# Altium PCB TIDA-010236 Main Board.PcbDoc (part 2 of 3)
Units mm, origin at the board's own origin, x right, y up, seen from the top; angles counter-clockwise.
Board outline 180 x 120 mm, 2 copper layers (Top Layer, Bottom Layer), stack 1.571 mm thick; 265 components, 145 nets, 704 pads, 547 vias.
Unrouted connection lines stored in the file: 155.
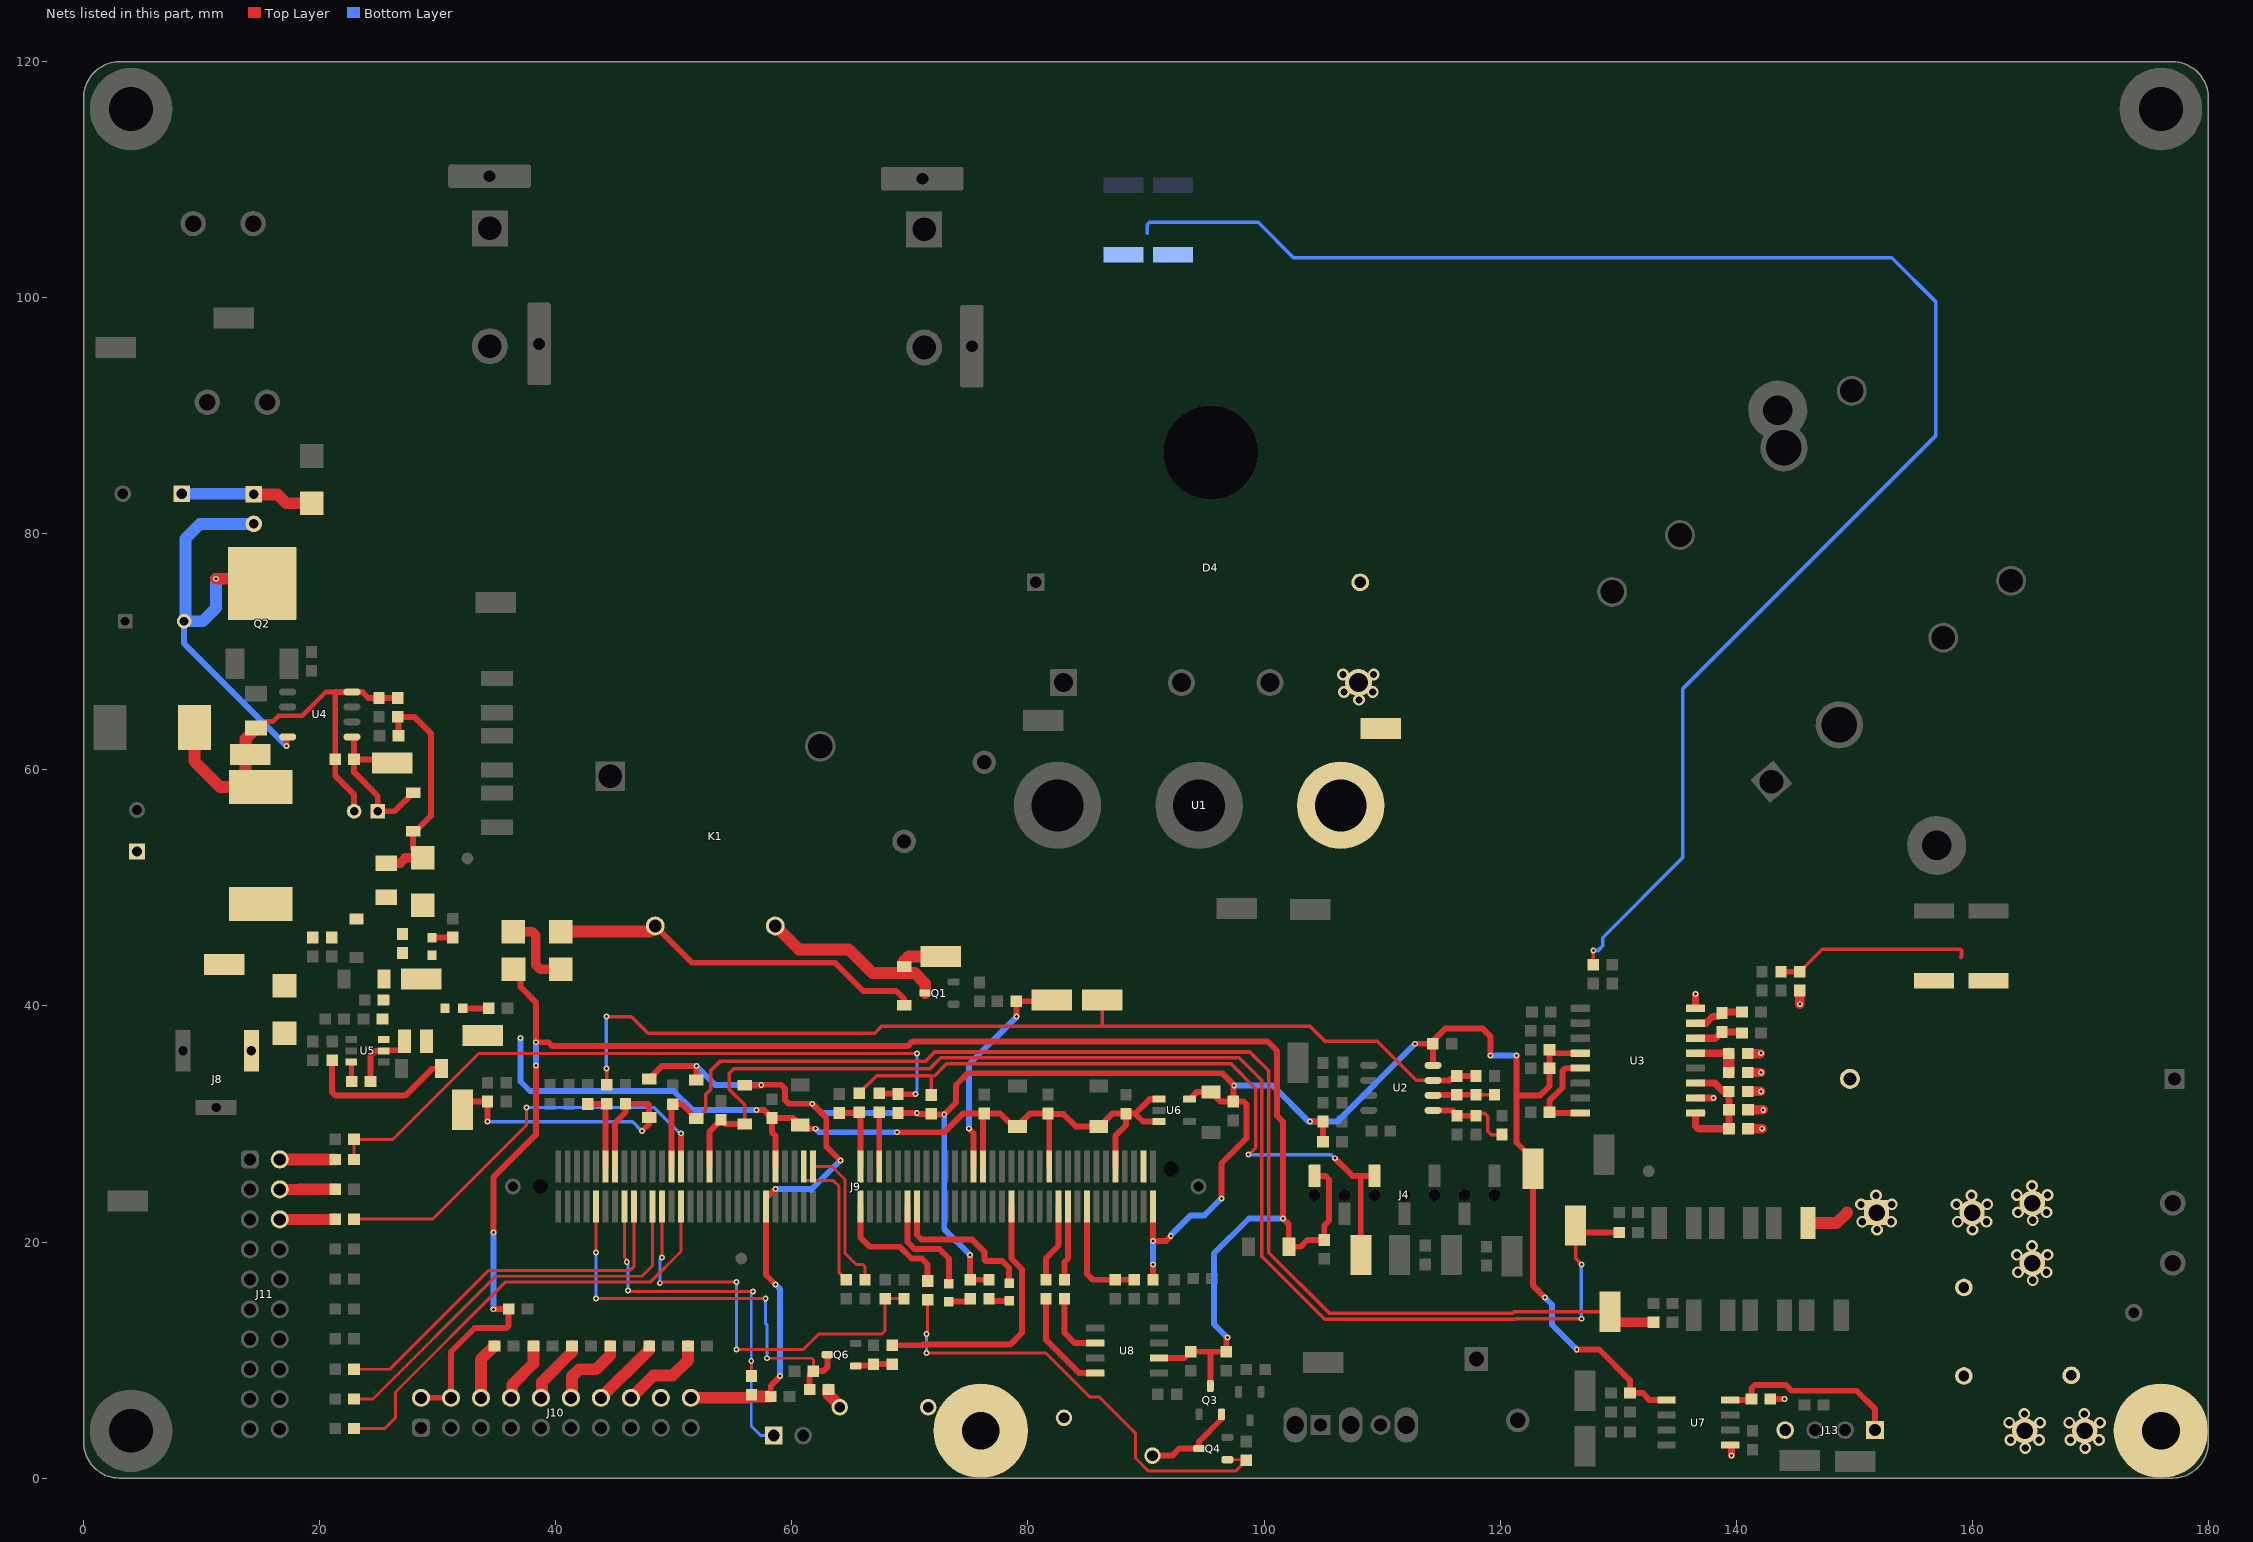
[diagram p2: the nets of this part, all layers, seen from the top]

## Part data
C1 C2: library part CMP-0094965-1, "WCAP-AIG5 Aluminum Electrolytic Capacitors 1000uF ±20% 450VDC", Leakage Current=2012uA, Manufacturer=Wurth, Operating Temperature Range="-25°C to +105°C", Tolerance_%=20%, ValueDisplayed=1000uF
C3 C4: library part ECAP1
C5: library part CMP-0012436-3, "CAP, Film, 2.2 uF, 630 V, +/- 20%, TH", Manufacturer=Panasonic, Tolerance_%=20%, Value1=Unknown, Value2=630V, ValueDisplayed=2.2uF
C6 C34 C35 C41 C42 C46 C50: library part CMP-0008965-2, "CAP, CERM, 10 uF, 25 V, +/- 10%, X7R, 1206", Cap_Case=2220, Manufacturer=MuRata, Supplier Part Number 1=81-GRM31CR71E106KA12, TempCo=X7R, Tolerance_%=10%, Value1=Unknown, Value2=25V, ValueDisplayed=10uF
C7 C9 C12 C13 C15 C17 C18 C26 C30 C33 C36 C40 C43 C45 C47 C49 C51 C52 C53: library part CMP-0007404-5, "CAP, CERM, 0.1 uF, 25 V, +/- 10%, X7R, 0603", Cap_Case=0603, Manufacturer=MuRata, Supplier Part Number 1=490-1524-1-ND, TempCo=X7R, Tolerance_%=10%, Value1=Unknown, Value2=25V, ValueDisplayed=0.1uF
C8 C22 C27 C28: library part CMP-0007433-4, "CAP, CERM, 0.01 uF, 50 V, +/- 10%, X7R, 0603", Cap_Case=0603, Manufacturer=MuRata, Supplier Part Number 1=490-1512-1-ND, TempCo=X7R, Tolerance_%=10%, Value1=Unknown, Value2=50V, ValueDisplayed=0.01uF
C10 C16 C19 C44 C48 C54 C55 C56 C58 C59 C63: library part CMP-0079720-2, "CAP, CERM, 1 µF, 25 V,+/- 10%, X7R, 0603", Cap_Case=0603, Manufacturer=MuRata, Supplier Part Number 1=490-10888-1-ND, TempCo=X7R, Tolerance_%=10%, Value2=25V, ValueDisplayed=1µF
C11 C14 C20 C65: library part CMP-0007432-5, "CAP, CERM, 1000 pF, 50 V, +/- 10%, X7R, 0603", Cap_Case=0603, Manufacturer=MuRata, Supplier Part Number 1=490-5768-2-ND, TempCo=X7R, Tolerance_%=10%, Value1=Unknown, Value2=50V, ValueDisplayed=1000pF
C21 C25: library part CMP-0007197-4, "CAP, CERM, 220 pF, 50 V, +/- 5%, C0G/NP0, 0603", Cap_Case=0603, Manufacturer=MuRata, Supplier Part Number 1=490-1435-1-ND, TempCo=C0G/NP0, Tolerance_%=5%, Value1=Unknown, Value2=50V, ValueDisplayed=220pF
C23: library part CMP-0007443-4, "CAP, CERM, 2200 pF, 50 V, +/- 10%, X7R, 0603", Cap_Case=0603, Manufacturer=MuRata, Supplier Part Number 1=490-1500-1-ND, TempCo=X7R, Tolerance_%=10%, Value1=Unknown, Value2=50V, ValueDisplayed=2200pF
C24: library part CMP-0007457-4, "CAP, CERM, 0.047 uF, 50 V, +/- 10%, X7R, 0603", Cap_Case=0603, Manufacturer=MuRata, Supplier Part Number 1=490-3287-1-ND, TempCo=X7R, Tolerance_%=10%, Value1=Unknown, Value2=50V, ValueDisplayed=0.047uF
C29: library part CMP-0007479-4, "CAP, CERM, 3300 pF, 100 V, +/- 10%, X7R, 0603", Cap_Case=0603, Manufacturer=MuRata, Supplier Part Number 1=490-1481-1-ND, TempCo=X7R, Tolerance_%=10%, Value1=Unknown, Value2=100V, ValueDisplayed=3300pF
C31: library part CMP-0010551-1, "CAP, AL, 10 uF, 35 V, +/- 20%, 0.95 ohm, TH", Cap_Case=5x7, Manufacturer=Nichicon, Supplier Part Number 1=493-1850-ND, Tolerance_%=20%, Value1="0.95 ohm", Value2=35V, ValueDisplayed=10uF
C32 C62: library part CMP-0007196-4, "CAP, CERM, 22 pF, 50 V, +/- 5%, C0G/NP0, 0603", Cap_Case=0603, Manufacturer=MuRata, Supplier Part Number 1=490-1411-1-ND, TempCo=C0G/NP0, Tolerance_%=5%, Value1=Unknown, Value2=50V, ValueDisplayed=22pF
C37: library part CMP-0093148-1, "15µF 450V Aluminum Electrolytic Capacitors Radial, Can 12000 Hrs @ 105°C", Digikey Part Number=493-13336-1-ND, Leakage Current=370uA, Manufacturer=Nichicon, Mouser Part Number=647-UCY2W150MPD1TD, Operating Temperature Range="-40°C to +105°C", Tolerance_%=20%, ValueDisplayed=15uF
C38: library part CMP-0010276-2, "CAP, AL, 4.7 uF, 450 V, +/- 20%, TH", Cap_Case=10x12.5mm, Manufacturer=Nichicon, Supplier Part Number 1=493-13004-1-ND, Tolerance_%=20%, Value1=Unknown, Value2=450V, ValueDisplayed=4.7uF
C39: library part CMP-0010536-1, "CAP, AL, 390 uF, 25 V, +/- 20%, 0.046 ohm, TH", Cap_Case=8x15, Manufacturer=Nichicon, Supplier Part Number 1=UHV1E391MPD-ND, Tolerance_%=20%, Value1="0.046 ohm", Value2=25V, ValueDisplayed=390uF
C57: library part CMP-0009589-2, "CAP, CERM, 4700 pF, 300 V, +/- 20%, Y5U, AEC-Q200 Grade 1, D13xT5mm", Cap_Case=13x5mm, Manufacturer=Vishay-Bccomponents, Supplier Part Number 1=BC2916-ND, TempCo=Y5U, Tolerance_%=20%, Value1=Unknown, Value2=300V, ValueDisplayed=4700pF
C60: library part CMP-0009606-4, "CAP, CERM, 100 pF, X1 250 VAC/Y2 300 VAC, +/- 10%, B, TH", Cap_Case=7x5x10mm, Manufacturer=MuRata, Supplier Part Number 1=490-9533-1-ND, TempCo=B, Tolerance_%=10%, Value1=Unknown, ValueDisplayed=100pF
C61: library part CMP-0007185-4, "CAP, CERM, 150 pF, 50 V, +/- 5%, C0G/NP0, 0603", Cap_Case=0603, Manufacturer=MuRata, Supplier Part Number 1=490-1431-1-ND, TempCo=C0G/NP0, Tolerance_%=5%, Value1=Unknown, Value2=50V, ValueDisplayed=150pF
C64: library part CMP-0090546-1, "1.2µF Film Capacitor 310V  Polypropylene (PP), Metallized Radial", Digikey Part Number=732-5766-ND, Manufacturer="Wurth Electronics", Mouser Part Number=710-890334027012CS, Operating Temperature Range="-40°C to +105°C", Tolerance_%=10%, ValueDisplayed=1.2uF
C66 C67: library part CMP-0006841-4, "CAP, CERM, 100 pF, 50 V, +/- 5%, C0G/NP0, 0603", Cap_Case=0603, Manufacturer=Kemet, Supplier Part Number 1=399-1061-1-ND, TempCo=C0G/NP0, Tolerance_%=5%, Value1=Unknown, Value2=50V, ValueDisplayed=100pF
C68 C69: library part CMP-0009611-1, "CAP, CERM, 4700 pF, 250 V, +/- 20%, E, 10x5x13mm", Cap_Case=10x5x13mm, Manufacturer=MuRata, Supplier Part Number 1=490-9484-ND, TempCo=E, Tolerance_%=20%, Value1=Unknown, Value2=250V, ValueDisplayed=4700pF
D1 D2: library part CMP-0078438-2, "Diode, Standard Recovery Rectifier, 1000 V, 1 A, SMA", Manufacturer="SMC Diode Solutions", Value1=1A, Value2=1.1V
D3 D6 D7 D8: library part CMP-0028457-2, "Diode, Schottky, 30 V, 0.2 A, SOD-123", Manufacturer="ON Semiconductor", Value1=0.2A, Value2=0.8V
D4: library part "Diode bridge", "Diode Bridge recotifier 1 phase 600V 25A TH", Manufacturer="Diodes Inc.", PartNumber=GBJ2506, Value1=25A, Value3=1.05V
D9: library part CMP-0029001-2, "Diode, Ultrafast, 100 V, 0.15 A, SOD-123", Manufacturer="Diodes Inc.", Value1=0.15A, Value2=1.25V
D10: library part CMP-0067545-2, "Diode, Superfast Rectifier, 600 V, 1 A, SMA", Manufacturer="SMC Diode Solutions", Value1=1A, Value2=1.7V
D11 D12: library part CMP-0078438-1, "Diode, Standard Recovery Rectifier, 1000 V, 1 A, SMA", Manufacturer="SMC Diode Solutions", Supplier Part Number 1=1655-1506-1-ND, Value1=1A, Value2=1.1V
D13 D17: library part CMP-0079921-3, "LED, Green, SMD", Color=Green, Manufacturer=Lite-On, Value1=W, Value2=2V
D14 D18: library part CMP-0079922-3, "LED, Red, SMD", Color=Red, Manufacturer=Lite-On, Value1=W, Value2=2V
D15: library part CMP-0005747-4, "Diode, Zener, 18 V, 700 mW, SOD-123", Manufacturer=Toshiba, Power_W=700mW, Value1=0.7W
D16: library part CMP-0076905-2, "Diode, Ultrafast, 600 V, 3 A, SMC", Manufacturer="ON Semiconductor", Value1=3A, Value2=1.25V
F1: library part CMP-4956-0000-1, "FUSE CERM 25A 250VAC 125VDC 3AB", Digikey Part Number=F3332-ND, Fuse Current=25A, Fuse Interrupt Dc Current=10000A, Manufacturer=Littelfuse, Mouser Part Number=576-0324025.MXP, Operating Temperature Range="-55°C to +125°C", Part Number=0324025.MXP, Supplier Part Number 1=F10249-ND
FID1 FID2 FID3: library part CMP-0077181-1, "Fiducial mark.  There is nothing to buy or mount.", Manufacturer=N/A
H1 H7: library part CMP-0003617-1, "Machine Screw, Round, #4-40 x 1/4, Nylon, Philips panhead", Manufacturer="B&F Fastener Supply", Supplier Part Number 1=H542-ND
H2 H3 H6: library part CMP-0003639-1, "Screw Pan Head M3", Manufacturer=Keystone, Supplier Part Number 1=36-29311-ND
H4 H5 H8 H9: library part CMP-0079094-1, "HEX STANDOFF M3 STEEL 12MM", Manufacturer="Wurth Elektronik", Supplier Part Number 1=732-10406-ND
J1 J2 J3 J5 J7: library part CMP-0089624-1, Current_A=20A, Digikey Part Number=A29938CT-ND, Manufacturer="TE Connectivity", Mouser Part Number=571-638241, Operating Temperature Range="-40°C to +105°C"
J4: library part CMP-0095208-1, Current_A=5.2A, Digikey Part Number=SSM-107-L-SV-BE-ND, Manufacturer=Samtec, Mouser Part Number=200-SSM107LSVBE, Operating Temperature Range="-55°C to +125°C", Voltage_V=572V
J6: library part CMP-0092874-1, Current_A=6A, Digikey Part Number=A123848-ND, Manufacturer="TE Connectivity AMP Connectors", Mouser Part Number=571-1-2834011-2, Operating Temperature Range="-40°C to +105°C", Voltage_V=300V
J8: library part CMP-0054778-3, "WR-DC DC Power Jack, R/A, TH", Color=Black, Manufacturer="Wurth Elektronik", Supplier Part Number 1=732-5930-ND
J9: library part controlCARD-120HSEC, "C2000 controlCARD-120HSEC connector, SMT", Manufacturer=Samtec
J10 J11: library part CMP-0086128-1, "Header(shrouded), 2.54mm, 10x2, Gold, TH", Color=Black, Current_A=3A, Manufacturer=Wurth, PartNumber=612020235121, Voltage_V=1kV
J12: library part CMP-0075223-1, "Header (Shrouded), 2.5mm, 2x1, Tin, TH", Color=White, Current_A=3A, Manufacturer="JST Manufacturing", Supplier Part Number 1=455-2247-ND, Voltage_V=250V
J13: library part CMP-0054954-3, "Header, 100mil, 4x1, Tin, TH", Manufacturer="TE Connectivity", Supplier Part Number 1=A30873-ND
K1: library part CMP-0078608-2, "Relay, SPST-NO (1 Form A), 30 A, 15 V, TH", Coil Current_A=66.7mA, Coil Power_W=1W, Coil Resistance_ohm=225, Coil Voltage_VDC=15V, Contact Rating_A=30A, Manufacturer="TE Connectivity", Turn Off Voltage (Min)_VDC=1.5V, Turn On Voltage (Max)_VDC=11.25V
L1: library part Boost_Inductor_250uH, "Inductor 265uH 26A vertical"
L2: library part CHOKE_PQ35, "PFC CHOKE 480uH 33A", Manufacturer=Sunlord
L3 L4 L5: library part CMP-0003277-1, "Ferrite Bead, 1800 ohm @ 100 MHz, 0.2 A, 0603", Manufacturer="Wurth Elektronik", Supplier Part Number 1=732-6695-1-ND, Value1="0.75 ohm", Value2=0.2A, ValueDisplayed="1800 ohm"
L6: library part CMP-0063792-1, "Inductor, Wirewound, Ferrite, 10 uH, 0.47 A, 0.435 ohm, SMD", Manufacturer="Wurth Elektronik", Supplier Part Number 1=732-5428-1-ND, Value1="0.435 ohm", Value2=0.47A, ValueDisplayed=10uH
L7: library part CMP-0064739-2, "Inductor, Unshielded Drum Core, Ferrite, 1 mH, 0.25 A, 4.38 ohm, TH", Manufacturer="Wurth Elektronik", Supplier Part Number 1=732-2576-ND, Value1="4.38 ohm", Value2=0.25A, ValueDisplayed=1mH
L8: library part CMP-0064531-2, "Inductor, Shielded Drum Core, Ferrite, 47 uH, 2.7 A, 0.076 ohm, SMD", Manufacturer="Wurth Elektronik", Supplier Part Number 1=732-1231-1-ND, Value1="0.076 ohm", Value2=2.7A, ValueDisplayed=47uH
LBL1: library part CMP-0003625-1, "Thermal Transfer Printable Labels, 0.650\" W x 0.200\" H - 10,000 per roll", Manufacturer=Brady, Supplier Part Number 1=97C5133
LOGO1 LOGO3: library part CMP-0074837-1, "IEC 61010-1 Hot Surface Warning"
LOGO2 LOGO4: library part CMP-0074835-1, "IEC 61010-1 High Voltage Warning"
Logo5: library part CMP-0074838-1, "Texas Instrument Corporate Signature"
Logo6: library part CMP-0074847-1, "FCC_disclaimer"
Logo7: library part CMP-0074769-1
MP1: library part CMP-0097532-1, "Main Heatsink", Manufacturer="Texas Instruments", Operating Temperature Range=to
Q1 Q3 Q4 Q5 Q6: library part CMP-0000777-1, "MOSFET, N-CH, 60 V, 0.32 A, AEC-Q101, SOT-23", Alternate Manufacturer=None, Manufacturer="ON Semiconductor", Supplier Part Number 1=2V7002KT1GOSCT-ND, Value1=2, Value2="0.7 nC"
Q2: library part CMP-0001138-4, "MOSFET, N-CH, 600 V, 4 A, DPAK", Alternate Manufacturer=None, Manufacturer=AOS, Supplier Part Number 1=785-1265-1-ND, Value2="6 nC"
R1: library part CMP-0023013-5, "RES, 300, 1%, 0.1 W, 0603", Manufacturer=Yageo, Power_W=100mW, Supplier Part Number 1=311-300HRCT-ND, TempCo="100 ppm/C", Tolerance_%=1%, Value2=0.1W, Value_Code=300R, ValueDisplayed=300
R2 R17 R22 R29 R34 R61 R65 R70 R73 R74 R79 R81: library part CMP-0022736-4, "RES, 100, 1%, 0.1 W, 0603", Manufacturer=Yageo, Power_W=100mW, Supplier Part Number 1=311-100HRCT-ND, TempCo="100 ppm/C", Tolerance_%=1%, Value2=0.1W, Value_Code=100R, ValueDisplayed=100
R3 R10 R11 R46 R47 R58 R67 R72: library part CMP-0022746-5, "RES, 10.0 k, 1%, 0.1 W, 0603", Manufacturer=Yageo, Power_W=100mW, Supplier Part Number 1=311-10.0KHRCT-ND, TempCo="100 ppm/C", Tolerance_%=1%, Value2=0.1W, Value_Code=10k0, ValueDisplayed=10.0k
R4 R5 R7 R8: library part CMP-0015819-2, "RES, 0.002, 1%, 1 W, 2512", Manufacturer=Panasonic, Power_W=1W, Supplier Part Number 1=P2.0NDCT-ND, TempCo=ppm/C, Tolerance_%=1%, Value_Code=2L000, ValueDisplayed=0.002
R6 R9 R55 R57: library part CMP-0022751-4, "RES, 10.0, 1%, 0.1 W, 0603", Manufacturer=Yageo, Power_W=100mW, Supplier Part Number 1=311-10.0HRCT-ND, TempCo="100 ppm/C", Tolerance_%=1%, Value2=0.1W, Value_Code=10R0, ValueDisplayed=10.0
R12 R36: library part CMP-0023166-5, "RES, 51.1 k, 1%, 0.1 W, 0603", Manufacturer=Yageo, Power_W=100mW, Supplier Part Number 1=311-51.1KHRCT-ND, TempCo="100 ppm/C", Tolerance_%=1%, Value2=0.1W, Value_Code=51k1, ValueDisplayed=51.1k
R13 R25 R45 R77: library part CMP-0022991-5, "RES, 2.40 k, 1%, 0.1 W, 0603", Manufacturer=Yageo, Power_W=100mW, Supplier Part Number 1=311-2.40KHRCT-ND, TempCo="100 ppm/C", Tolerance_%=1%, Value2=0.1W, Value_Code=2k40, ValueDisplayed=2.40k
R14 R15 R16 R26 R27 R28 R31 R32 R33: library part CMP-0083082-1, "RES, 330 k, 1%, 0.5 W, 1210", Manufacturer=Yageo, Power_W=500mW, TempCo="100 ppm/C", Tolerance_%=1%, Value2=0.5W, Value_Code=330k
R18 R21 R30 R35 R44: library part CMP-0023198-5, "RES, 5.10 k, 1%, 0.1 W, 0603", Manufacturer=Yageo, Power_W=100mW, Supplier Part Number 1=311-5.10KHRCT-ND, TempCo="100 ppm/C", Tolerance_%=1%, Value2=0.1W, Value_Code=5k10, ValueDisplayed=5.10k
R19 R23: library part CMP-0023081-5, "RES, 3.30 k, 1%, 0.1 W, 0603", Manufacturer=Yageo, Power_W=100mW, Supplier Part Number 1=311-3.30KHRCT-ND, TempCo="100 ppm/C", Tolerance_%=1%, Value2=0.1W, Value_Code=3k30, ValueDisplayed=3.30k
R20 R24 R41 R48 R49 R50 R51 R52 R54 R56 R59 R60 R62 R64 R66 R68 R69 R71 R82 R84 R85 R86 R88: library part CMP-0025885-5, "RES, 0, 5%, 0.1 W, 0603", Manufacturer=Yageo, Power_W=100mW, Supplier Part Number 1=311-0.0GRCT-ND, TempCo="200 ppm/C", Tolerance_%=5%, Value2=0.1W, Value_Code=0000, ValueDisplayed=0
R37: library part CMP-0074670-1, "RES, 0.3, 1%, 0.5 W, AEC-Q200 Grade 1, 1206", Manufacturer=Panasonic, Power_W=500mW, Supplier Part Number 1=P17626CT-ND, TempCo="250 ppm/C", Tolerance_%=1%, Value2=0.5W, Value_Code=R300, ValueDisplayed=0.3
R38: library part CMP-0018293-2, "RES, 430 k, 1%, 0.25 W, 1206", Manufacturer="Yageo America", Power_W=250mW, Supplier Part Number 1=311-430KFRCT-ND, TempCo="100 ppm/C", Tolerance_%=1%, Value2=0.25W, Value_Code=430k
R39: library part CMP-0022851-5, "RES, 18.7 k, 1%, 0.1 W, 0603", Manufacturer=Yageo, Power_W=100mW, Supplier Part Number 1=311-18.7KHRCT-ND, TempCo="100 ppm/C", Tolerance_%=1%, Value2=0.1W, Value_Code=18k7, ValueDisplayed=18.7k
R40: library part CMP-0023304-5, "RES, 88.7 k, 1%, 0.1 W, 0603", Manufacturer=Yageo, Power_W=100mW, Supplier Part Number 1=311-88.7KHRCT-ND, TempCo="100 ppm/C", Tolerance_%=1%, Value2=0.1W, Value_Code=88k7, ValueDisplayed=88.7k
R42: library part CMP-0022779-5, "RES, 12.0 k, 1%, 0.1 W, 0603", Manufacturer=Yageo, Power_W=100mW, Supplier Part Number 1=311-12.0KHRCT-ND, TempCo="100 ppm/C", Tolerance_%=1%, Value2=0.1W, Value_Code=12k0, ValueDisplayed=12.0k
R43 R53 R63 R75 R76 R78 R80 R83: library part CMP-0022895-5, "RES, 1.00 k, 1%, 0.1 W, 0603", Manufacturer=Yageo, Power_W=100mW, Supplier Part Number 1=311-1.00KHRCT-ND, TempCo="100 ppm/C", Tolerance_%=1%, Value2=0.1W, Value_Code=1k00, ValueDisplayed=1.00k
R87: library part CMP-0022883-5, "RES, 1.50 k, 1%, 0.1 W, 0603", Manufacturer=Yageo, Power_W=100mW, Supplier Part Number 1=311-1.50KHRCT-ND, TempCo="100 ppm/C", Tolerance_%=1%, Value2=0.1W, Value_Code=1k50, ValueDisplayed=1.50k
RT1: library part B59751B0120A070, "Thermistor PTC, 50 ohm, 25%, D23 x T10mm, P7.8mm", Manufacturer=Ametherm, Supplier Part Number 1=570-1117-ND, Tolerance_%=25
S1: library part CMP-0091791-1, "Toggle Switch SPDT Through Hole  3A 120V", Contact Current Rating=3A, Digikey Part Number=EG5771-ND, Manufacturer=E-Switch, Mouser Part Number=612-200AWMSP1T1A1M2Q, Operating Temperature Range="-30°C to +85°C"
TP1 TP2 TP3 TP4 TP5 TP6 TP7 TP8 TP9 TP10 TP11 TP12 TP13 TP14 TP15 TP17 TP18 TP19 TP20 TP21 TP22 TP23 TP25 TP26 TP28 TP29 TP30 TP31 TP32 TP33 TP34: library part CMP-0055152-1, "Test Point, Miniature, SMT", Manufacturer=Keystone, Supplier Part Number 1=36-5015TR-ND
U1: library part GaN_Daughter_Board_2
U2: library part CMP-0013007-4, "10-MHz, Low-Noise, RRIO, CMOS Operational Amplifier for Cost-Sensitive Systems, D0008A (SOIC-8)", Alternate Manufacturer="Texas Instruments", Alternate PartNumber=TLV9062ID, Operating Temperature Range="-40 to 125 C", Rating=Catalog
U3: library part CMP-0089607-3, "Precision, ±250-mV Input, Reinforced Isolated Amplifier With Integrated DC/DC Converter", Manufacturer="Texas Instruments", Max Supply Voltage=5.5V, Min Supply Voltage=3V, Nominal Supply Current=27.5-28.5mA, Operating Temperature Range="-40°C to +125°C"
U4: library part CMP-0067230-2, "Constant-Voltage, Constant-Current PWM Controller with Primary-Side Regulation, D0007A (SOIC-7)", Alternate Manufacturer="Texas Instruments", Alternate PartNumber=UCC28710D
U5: library part CMP-0073969-3, "4.5V to 28V Input, 2A Output, EMI Friendly Synchronous Step-Down Converter, DDC0006A (SOT-23-THIN-6)", Alternate Manufacturer="Texas Instruments", Alternate PartNumber=TPS54202DDCT, Operating Temperature Range="-40 to 125 C", Rating=Catalog
U6: library part CMP-0090171-1, "300-mA low-dropout (LDO) regulator with foldback current limit 5-SOT-23 -40 to 125", Digikey Part Number=296-TLV74033PDBVRCT-ND, Dropout Voltage=460mV, Manufacturer="Texas Instruments", Max Supply Voltage=5.5V, Mouser Part Number=595-TLV74033PDBVR, Nominal Supply Current=50uA, Operating Temperature Range="-40°C to +125°C", Output Voltage=3.3V
U7: library part CMP-0089949-1, "Low Speed, General Purpose, Robust EMC, Dual-Channel Digital Isolators", Manufacturer="Texas Instruments", Max Supply Voltage=5.5V, Min Supply Voltage=1.71V, Operating Temperature Range="to +150°C"
U8: library part CMP-0091920-1, "Dual Channel 30-V 5-A High-Speed Low-Side Gate Driver", Manufacturer="Texas Instruments", Max Supply Voltage=26V, Min Supply Voltage=4.5V, Nominal Supply Current=175uA, Operating Temperature Range="-40°C to +150°C"

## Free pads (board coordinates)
  oval 2x3 hole 1.5 slot 2.5 at 90 deg: 2(102.64,4.5) 2(112.04,4.5)

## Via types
v1: diameter 1, hole 0.6, Top Layer to Bottom Layer, 286 vias
v2: diameter 0.5, hole 0.25, Top Layer to Bottom Layer, 261 vias

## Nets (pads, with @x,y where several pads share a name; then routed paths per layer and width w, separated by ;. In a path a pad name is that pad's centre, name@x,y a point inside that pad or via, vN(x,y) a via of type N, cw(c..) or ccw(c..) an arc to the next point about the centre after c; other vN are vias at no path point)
3V3: C9.1 C13.1 C19.1 C20.2 C41.1 C43.1 C54.1 C58.1 D6.1 D7.1 D8.1 J9.45 J9.119 J10.18 J10.20 R10.2 R53.2 R58.2 R67.2 R72.2 R76.2 R77.2 TP15.1 U2.8 U3.12 U6.5 U7.1 | length 224.1
  Top Layer w0.5: D8.1@47.9,33.825 48.975,34.9 v2(51.9,34.9) D7.1@51.9,33.737 ; D6.1@56,33.275 57.375,33.275 v2(57.4,33.3) 57.427,33.327 59.073,33.327 59.4,33 59.4,32.057 59.739,31.717 v2(61.72,31.717) 62.91,30.527 62.91,28.09 v2(64.1,26.9) ; C58.1@58.2,6.901 58.2,7.834 v2(59,8.634) ; v2(58.6,16.4) 57.8,17.2 J9.45@57.8,23 57.8,23.7 v2(58.6,24.5) ; R67.2@68.978,30.94 v2(70.577,30.94) 70.667,30.85 R58.2@71.788,30.85 ; R58.2@71.8,30.862 71.862,30.8 v2(72.906,30.8) 73.903,31.797 73.903,33.303 74.9,34.3 96.45,34.3 v2(97.475,33.275) ; v2(75.1,18.9) R76.2@75.1,16.8 R77.2@76.7,16.8 ; R72.2@90.6,16.8 v2(90.6,18.1) ; J9.119@90.6,23 v2(90.6,20.1) 91.7,20.1 v2(92.1,20.5) ; U6.5@93.7,32.106 94.294,32.7 C41.1@95.5,32.7 96.3,31.9 C43.1@97.4,31.9 ; v2(96.4,23.7) 96.4,26.668 98.5,28.769 98.5,31.675 98.275,31.9 C43.1@97.4,31.9 ; v2@97.4,33.2 C43.1@97.4,31.9 ; v2(103.9,30.2) R10.2@105,30.2 C13.1@105,28.5 ; v2(112.8,36.8) C9.1@114.3,36.8 ; U2.8@114.325,34.966 114.325,36.775 C9.1@114.3,36.8 ; v2(119.2,35.8) 119.2,37.4 118.5,38.1 115.4,38.1 114.3,37 C9.1@114.3,36.8 ; v2(121.4,35.8) 121.4,32.4 ; v2(123.8,15.3) 122.8,16.3 TP15.1@122.8,26.2 122.8,27.026 121.4,28.426 121.4,32.4 ; v2(126.5,10.9) 128.4,10.9 131,8.3 C54.1@131,7.2 132.1,7.2 132.695,6.605 U7.1@134.1,6.605 ; U3.12@126.811,35.997 124.502,35.997 C20.2@124.2,36.3 C19.1@124.2,34.727 124.2,33.226 123.374,32.4 121.4,32.4
  Top Layer w1: J10.20@51.43,6.8 56.322,6.8 R53.2@56.58,7.058 56.737,6.901 C58.1@58.2,6.901
  Bottom Layer w0.5: v2(51.9,34.9) 53.5,33.3 v2(57.4,33.3) ; v2(58.6,16.4) 59,16 v2(59,8.634) ; v2(58.6,24.5) 61.5,24.5 61.6,24.4 v2(64.1,26.9) ; v2(61.72,31.717) 62.498,30.94 v2(70.577,30.94) ; v2(72.906,30.8) 72.906,21.094 v2(75.1,18.9) ; v2(90.6,18.1) v2(90.6,20.1) ; v2(92.1,20.5) 92.1,20.576 93.783,22.258 94.958,22.258 v2(96.4,23.7) ; v2(97.475,33.275) 100.725,33.275 103.8,30.2 v2(103.9,30.2) 106.2,30.2 v2(112.8,36.8) ; v2(119.2,35.8) v2(121.4,35.8) ; v2(123.8,15.3) 124.4,14.7 124.4,13 v2(126.5,10.9)
5V: C34.1 C42.1 C46.2 C47.2 C50.1 C51.1 C52.1 C53.1 D13.1 J9.48 J9.84 J9.98 J9.112 L6.2 R40.2 TP23.1 U6.1 U6.3 | length 96.1
  Top Layer w0.5: R40.2@21.039,35.4 21.039,32.693 21.332,32.4 27.224,32.4 29.508,34.684 30.283,34.684 C34.1@30.3,34.701 ; v2(57,31.2) 57.6,31.2 C47.2@58.3,30.5 ; J9.48@58.6,26.4 58.6,29 58.3,29.3 C47.2@58.3,30.5 ; v2(62,29.6) 61,29.6 60.1,30.5 C47.2@58.3,30.5 ; v2(68.9,29.3) 72.906,29.3 74.506,30.9 77.626,30.9 78.726,29.8 C50.1@79.1,29.8 80.2,30.9 C51.1@81.7,30.9 C51.1@81.75,30.85 ; J9.84@76.2,26.4 C53.1@76.2,30.8 ; J9.98@81.8,26.4 81.8,30.8 C51.1@81.75,30.85 ; C42.1@86.037,29.763 85.974,29.7 C42.1@85.874,29.8 ; J9.112@87.4,26.4 87.4,29 88.3,29.9 C52.1@88.3,30.875 ; U6.3@91.1,30.206 89.743,30.206 89.075,30.875 ; U6.1@91.1,32.106 90.307,32.106 89.075,30.875 ; C51.1@81.75,30.85 83,30.85 84.05,29.8 C42.1@85.874,29.8 ; C42.1@85.874,29.8 C42.1@86,29.8 86.074,29.8 87.148,30.875 C52.1@88.3,30.875 ; C52.1@88.3,30.875 89.075,30.875
  Bottom Layer w0.5: v2(37,37.3) 37,33.6 37.8,32.8 49.956,32.8 51.556,31.2 v2(57,31.2) ; v2(62,29.6) 62.3,29.3 v2(68.9,29.3)
5V_ISO: C55.1 J13.1 U7.8 | length 16
  Top Layer w0.5: U7.8@139.5,6.605 141.205,6.605 C55.1@141.3,6.7 141.3,7.6 141.6,7.9 144.2,7.9 144.7,7.4 150.2,7.4 151.78,5.82 J13.1@151.78,4.065
15V: C6.1 C7.1 C35.1 C36.1 C56.1 C59.1 C63.1 D2.2 D14.1 J4.7 J10.2 J10.4 Q3.3 R12.2 R41.2 TP22.1 U5.3 U8.6 | length 161.1
  Top Layer w0.5: J10.2@28.57,6.8 J10.4@31.11,6.8 31.11,10.703 33.107,12.7 35.796,12.7 35.996,12.9 35.996,14.33 C63.1@36,14.333 34.74,14.333 v2(34.707,14.3) ; v2(34.7,20.82) 34.7,25.5 38.3,29.1 v2(38.3,34.966) ; D2.2@36.407,43.1 37,42.507 37,41.618 38.3,40.318 v2(38.3,36.927) 39.373,36.927 39.7,36.6 69.8,36.6 70.2,37 100.3,37 101.1,36.2 101.1,30.7 101.6,30.2 v2(101.6,22) 102.1,21.5 C6.1@102.1,19.6 103.1,19.6 103.68,20.18 C7.1@105.1,20.18 105.1,21.4 105.5,21.8 105.5,25.3 105.198,25.602 J4.7@104.28,25.603 ; U8.6@91.1,10.165 93.265,10.165 C59.1@93.8,10.7 95.5,10.7 ; Q3.3@95.45,7.8 95.45,10.65 95.5,10.7 ; v2(96.9,11.9) 96.8,11.8 C56.1@96.8,10.7 95.5,10.7
  Bottom Layer w0.5: v2(34.7,20.82) 34.7,14.307 v2(34.707,14.3) ; v2(38.3,34.966) v2(38.3,36.927) ; v2(96.9,11.9) 95.75,13.05 95.75,19.025 98.725,22 v2(101.6,22)
/FAULT: J4.5 R58.1 R61.2 TP11.1 | length 61.2
  Top Layer w0.3: R61.2@65.7,32.6 65.7,32.625 67.175,34.1 71.788,34.1 71.8,34.088 R58.1@71.8,32.462 71.95,32.312 R58.1@72.1,32.462 ; 72.1,34.1 73.1,35.1 97.2,35.1 99.3,33 99.3,28 v2(98.7,27.4)
  Top Layer w0.5: v2(106,27.1) 107.498,25.602 108.2,25.602 ; TP11.1@108.2,18.9 108.2,25.602 ; J4.5@109.36,25.603 108.2,25.602
  Bottom Layer w0.3: v2(98.7,27.4) 105.7,27.4 v2(106,27.1)
ACTIVE_EMI_RESET: J9.89 R88.1 | length 22.5
  Top Layer w0.5: R88.1@68.49,11.25 71.06,11.25 71.11,11.3 78.49,11.3 79.5,12.31 79.5,17.69 78.6,18.59 J9.89@78.6,23
ACTIVE_EMI_SENSE: C61.1 J9.9 Q6.3 R87.2 | length 36.3
  Top Layer w0.25: v2(43.4,15.2) v2(57.776,15.2) ; v2(43.4,19.1) J9.9@43.4,23 ; v2(57.9,10.15) 61.661,10.15 61.807,10.004 C61.1@61.807,9.055
  Top Layer w0.5: R87.2@61.5,7.5 61.5,8.773 61.782,9.055 C61.1@61.807,9.055 62.655,9.055 63,9.4 Q6.3@63,10.45
  Bottom Layer w0.25: v2(43.4,15.2) v2(43.4,19.1) ; v2(57.776,15.2) 57.776,13.07 57.9,12.945 v2(57.9,10.15)
ANA_Iac: C24.1 J9.12 R22.2 | length 6.9
  Top Layer w0.5: C24.1@42.7,31.7 R22.2@44.283,31.7 ; J9.12@44.2,26.4 44.2,31.617 R22.2@44.283,31.7 ; R22.2@44.3,31.717 R22.2@44.283,31.7
ANA_VacL: C22.1 D6.2 J9.34 R17.2 TP18.1 | length 114.1
  Top Layer w0.3: D6.2@56,30 56,31.626 54.7,32.926 54.7,34.3 55.1,34.7 71.7,34.7 72.6,35.6 97.9,35.6 99.8,33.7 99.8,18.8 105.15,13.45 121.281,13.45 121.331,13.5 v2(126.892,13.5) ; TP18.1@126.4,21.4 126.4,18.6 v2(126.9,18.1)
  Top Layer w0.5: J9.34@53,26.4 53,29.356 C22.1@54,30.356 54.357,30 D6.2@56,30 ; TP18.1@126.4,21.4 127,20.8 128.5,20.8 R17.2@130.1,20.8
  Bottom Layer w0.3: v2(126.892,13.5) 126.892,18.092 v2(126.9,18.1)
ANA_VacN: C28.1 D7.2 J9.26 R29.2 TP19.1 | length 111.6
  Top Layer w0.3: D7.2@51.9,30.463 52.006,30.463 52.7,31.156 52.7,32.5 53.1,32.9 53.1,34.5 53.9,35.3 71.3,35.3 72.1,36.1 98.8,36.1 100.4,34.5 100.4,20.7 100.4,19.1 105.55,13.95 121.074,13.95 121.224,14.1 TP19.1@129.3,14.1
  Top Layer w0.5: J9.26@49.8,26.4 49.8,31.575 C28.1@49.9,31.675 50.688,31.675 D7.2@51.9,30.463
  Top Layer w0.8: TP19.1@129.3,14.1 130.2,13.2 131.4,13.2 R29.2@133,13.2
ANA_Vdc: C29.1 D8.2 J9.14 R34.2 TP20.1 | length 27.7
  Top Layer w0.5: TP20.1@32.1,31.9 33.6,31.9 R34.2@34.2,31.9 v2(34.2,30.206) ; TP20.1@32.425,30.6 TP20.1@32.625,30.8 ; J9.14@45,26.4 45,30.1 45.9,31 C29.1@45.9,31.717 47.783,31.717 47.9,31.6 D8.2@47.9,30.55 47.9,30 v2(47.3,29.4)
  Bottom Layer w0.3: v2(34.2,30.206) 34.207,30.2 46.5,30.2 v2(47.3,29.4)
EARTH: C68.2 C69.1 H7.1 J2.1
  other v1: 164.5,2.543 169.58,2.543 163.25,3.218 165.675,3.218 168.33,3.218 170.755,3.218 163.15,4.693 165.75,4.693 168.23,4.693 170.83,4.693 164.425,5.443 169.505,5.443
EARTH1: C57.2 C60.1 H1.1 | length 2.8
  Top Layer w2: H1.1@74.1,3.1 76,5 H1.1@76.1,5.1
GaN_TEMP: C44.1 J9.23 R46.2 | length 36.4
  Top Layer w0.25: v2(48.8,16.51) 48.89,16.6 v2(55.3,16.6) ; v2(49,18.7) J9.23@49,23 ; v2(55.3,10.89) 60.955,10.89 62.265,12.2 67.605,12.2 67.9,12.495 C44.1@67.9,15.2 R46.2@69.5,15.2
  Bottom Layer w0.25: v2(48.8,16.51) 48.8,18.5 v2(49,18.7) ; v2(55.3,10.89) v2(55.3,16.6)
GND_ISO: C55.2 J13.4 U7.5 | length 2.1
  Top Layer w0.5: C55.2@142.9,6.7 v2(144.1,6.7)
  Top Layer w0.6: U7.5@139.5,2.795 139.6,2.695 v2(139.6,1.9)
Heatsink_Temp: J9.15 J12.1 R53.1 | length 33.1
  Top Layer w0.25: J9.15@45.8,23 45.8,18.7 46,18.5 v2(46,18.3) ; v2(46.1,15.9) 46.2,16 46.4,15.8 v2(56.7,15.8) ; v2(56.55,9.925) 56.55,8.688 R53.1@56.58,8.658
  Bottom Layer w0.25: v2(46,18.3) 46.1,18.4 v2(46.1,15.9) ; v2(56.7,15.8) 56.7,15.732 56.55,15.582 56.55,4.41 57.36,3.6 J12.1@58.45,3.6
Idc: C5.2 D4.4 R4.1 R5.1 R20.1 TP13.1 U1.3 | length 138.8
  Top Layer w0.3: R20.1@127.9,43.5 v2(127.9,44.7)
  Bottom Layer w0.3: 90.1,105.499 90.1,106.2 90.3,106.4 99.5,106.4 102.5,103.4 153.2,103.4 156.9,99.7 156.9,88.3 135.5,66.9 135.5,52.595 128.7,45.795 128.7,45.098 128.302,44.7 v2(127.9,44.7)
  other v1: 108.04,65.943 106.79,66.618 109.215,66.618 106.69,68.093 109.29,68.093
INJ_PD_LEVEL: C48.1 Q4.1 R63.2 | length 39.1
  Top Layer w0.25: v2(71.4,10.6) 81.5,10.6 85.25,6.85 86.05,6.85 89.1,3.8 89.1,1.7 90.2,0.6 97.6,0.6 C48.1@98.5,1.5 98.45,1.55 Q4.1@96.9,1.55 ; v2(71.4,12.2) 71.5,12.3 R63.2@71.5,15.1
  Bottom Layer w0.25: v2(71.4,10.6) 71.4,12.254 v2(71.4,12.2)
INJ_PD_PULSE: R73.1 U8.2 | length 5.9
  Top Layer w0.5: R73.1@83.1,15.2 83.1,12.3 83.965,11.435 U8.2@85.7,11.435
INJ_PU_PULSE: R70.1 U8.4 | length 8.8
  Top Layer w0.5: R70.1@81.527,15.2 81.527,11.709 84.34,8.895 U8.4@85.7,8.895
INRUSH_CTRL: J9.82 R2.2 TP12.1 | length 18.9
  Top Layer w0.5: v2(75,29.6) 75.4,29.2 J9.82@75.4,26.4 ; v2(79.035,39.1) 79.035,40.365 R2.2@79,40.4 81.9,40.4 TP12.1@82,40.5
  Bottom Layer w0.5: v2(75,29.6) 75,35.065 v2(79.035,39.1)
IPM_Temp: J9.28 R69.1 | length 36.2
  Top Layer w0.25: R69.1@22.9,21.933 29.533,21.933 37.5,29.9 v2(37.5,31.4)
  Top Layer w0.5: J9.28@50.6,26.4 v2(50.6,29.212)
  Bottom Layer w0.25: v2(37.5,31.4) 48.265,31.4 48.282,31.418 50.488,29.212 v2(50.6,29.212)
Iu: J9.27 R56.1 | length 39
  Top Layer w0.25: R56.1@22.9,4.2 25.5,4.2 26.4,5.1 26.4,7.3 35.7,16.6 48,16.6 50.6,19.2 J9.27@50.6,23
Iv: J9.21 R59.1 | length 35
  Top Layer w0.25: R59.1@22.9,6.7 24.5,6.7 34.9,17.1 47.282,17.1 48.2,18.018 J9.21@48.2,23
Iw: J9.17 R60.1 | length 32.4
  Top Layer w0.25: R60.1@22.9,9.22 25.92,9.22 34.3,17.6 46.3,17.6 46.6,17.9 J9.17@46.6,23
LED_GREEN: D17.2 J9.67 | length 9.2
  Top Layer w0.5: J9.67@69.8,23 69.8,20 70.4,19.4 72.5,19.4 73.3,18.6 D17.2@73.3,16.45
LED_RED: D18.2 J9.69 | length 13
  Top Layer w0.5: J9.69@70.6,23 70.6,20.6 71,20.2 75.275,20.2 76.3,19.175 76.3,18.5 76.4,18.4 77.8,18.4 78.4,17.8 D18.2@78.4,16.51
LINE_Filtered: C68.1 F1.2 J1.1
  other v1: 165.14,16.763 163.89,17.438 166.315,17.438 163.79,18.913 166.39,18.913 165.065,19.663 160.033,21.043 158.783,21.718 161.208,21.718 165.14,21.843 163.89,22.518 166.315,22.518 158.683,23.193 161.283,23.193 159.958,23.943 163.79,23.993 166.39,23.993 165.065,24.743
LINE_Filtered1: C64.2 F1.1 L3.2 L5.2 R7.1 R8.1 R14.1 | length 20.4
  Top Layer w0.3: L3.2@145.4,42.9 147.3,44.8 159,44.8 159.1,44.7 159.1,44.18 159.02,44.1
  Top Layer w0.5: L5.2@143.8,42.9 L3.2@145.4,42.9
  Top Layer w1: R14.1@146.1,21.6 148.5,21.6 149.4,22.5
  other v1: 151.94,21.043 150.69,21.718 153.115,21.718 150.59,23.193 153.19,23.193 151.865,23.943
MCU1V2: J9.118
Motor_Fault: C65.2 R65.2 R67.1 R74.1 | length 59
  Top Layer w0.25: R74.1@22.9,27 C65.2@22.9,28.7 26.2,28.7 33.462,35.962 v2(70.6,35.962) ; R67.1@68.955,32.517 R67.1@68.978,32.54
  Top Layer w0.5: R65.2@67.4,32.6 67.43,32.57 68.925,32.57 R67.1@68.967,32.529 ; R67.1@68.955,32.517 70.455,32.517 v2(70.478,32.54)
  Bottom Layer w0.25: v2(70.478,32.54) 70.478,32.607 70.6,32.73 v2(70.6,35.962)
NetC8_1: C8.1 R6.2 U3.7 | length 4.3
  Top Layer w0.6: U3.7@136.561,38.537 137.437,38.537 138,39.1 138.5,39.1 C8.1@138.8,39.4 138.9,39.5 R6.2@140.5,39.5
NetC8_2: C8.2 R9.2 U3.6 | length 4.2
  Top Layer w0.6: U3.6@136.561,37.267 138.267,37.267 C8.2@138.8,37.8 140.4,37.8 R9.2@140.5,37.7
NetC10_1: C10.1 C11.1 C12.2 U3.1 U3.3 | length 10.9
  Top Layer w0.6: U3.3@136.561,33.457 138.2,33.457 138.895,32.762 C12.2@139.386,32.762 139.4,32.748 C11.1@139.4,31.2 C10.1@139.4,29.6 136.8,29.6 136.561,29.839 U3.1@136.561,30.917 U3.1@137.145,30.917
NetC10_2: C10.2 C11.2 C12.1 C14.1 C18.1 L3.1 U3.2 U3.8 | length 9.7
  Top Layer w0.4: v2@142.065,35.962 v2(142.1,35.997)
  Top Layer w0.6: U3.2@136.561,32.187 136.573,32.2 v2(138.1,32.2) ; U3.8@136.561,39.807 v2(136.561,41)
  Top Layer w0.8: C12.1@140.986,32.762 v2(142.1,32.762) ; C18.1@140.986,34.361 v2(142.1,34.361) ; C14.1@140.986,35.962 v2@142.065,35.962 ; C10.2@141,29.6 v2(142.2,29.6) ; C11.2@141,31.2 v2(142.3,31.2) ; v2(145.4,40.15) L3.1@145.4,41.3
NetC14_2: C14.2 C18.2 U3.5 | length 4.4
  Top Layer w0.6: U3.5@136.561,35.997 139.351,35.997 C14.2@139.386,35.962
  Top Layer w1: C18.2@139.386,34.361 C14.2@139.386,35.962
NetC15_1: C15.1 U3.13 U3.16 | length 8.2
  Top Layer w0.5: U3.16@126.811,30.917 124.283,30.917 C15.1@124.2,31 124.2,32 125.3,33.1 125.3,34.5 125.527,34.727 U3.13@126.811,34.727
NetC21_1: C21.1 R13.1 R22.1 TP17.1 U2.7 | length 84.6
  Top Layer w0.3: v2(44.283,34.701) 44.3,34.684 R22.1@44.3,33.317 ; v2(44.3,39.1) 46.4,39.1 47.8,37.7 67.02,37.7 67.62,38.3 86.2,38.3 ; TP17.1@86.3,40.5 86.3,38.4 86.2,38.3 ; U2.7@114.325,33.696 112.904,33.696 109.6,37 105.163,37 103.862,38.3 86.2,38.3
  Top Layer w0.5: U2.7@114.325,33.696 115.696,33.696 115.825,33.825 116.1,33.825 116.325,34.05 R13.1@116.325,34.075 C21.1@117.953,34.075
  Bottom Layer w0.3: v2(44.283,34.701) 44.283,39.083 v2(44.3,39.1)
NetC21_2: C21.2 R13.2 R19.2 U2.6 | length 5.2
  Top Layer w0.3: C21.2@117.953,32.475 118.71,32.475 R19.2@119.541,32.475
  Top Layer w0.5: U2.6@114.325,32.426 114.344,32.446 116.296,32.446 R13.2@116.325,32.475 C21.2@117.953,32.475
NetC23_2: C23.2 J9.58 R61.1 | length 6.5
  Top Layer w0.5: C23.2@64,30.94 R61.1@65.307,30.94 ; R61.1@65.7,31 65.516,31 65.307,31 65.516,30.791 65.8,30.507 J9.58@65.8,26.4
NetC25_1: C25.1 R23.2 R25.2 U2.5 | length 7.7
  Top Layer w0.3: C25.1@117.953,30.7 118.144,30.891 118.702,30.891 118.976,30.617 118.976,29.374 119.25,29.1 R23.2@120.175,29.1
  Top Layer w0.5: U2.5@114.325,31.156 116.018,31.156 116.018,31.056 116.35,30.725 R25.2@116.35,30.7 117.762,30.7 C25.1@117.908,30.845
NetC30_1: C30.1 C31.1 D9.1 TP21.1 U4.1 | length 14.2
  Top Layer w0.5: U4.1@22.718,62.795 22.9,62.613 C30.1@22.9,60.9 ; TP21.1@26.15,60.6 25.85,60.9 C30.1@22.9,60.9 ; D9.1@27.9,58.075 26.325,56.5 C31.1@24.9,56.5 24.9,57.8 22.9,59.8 C30.1@22.9,60.9
NetC30_2: C30.2 C31.2 C32.2 D16.1 L8.1 R37.2 R39.1 TP25.1 U4.4 | length 39
  Top Layer w0.4: R37.2@14.6,63.55 14.885,63.55 15.435,64.1 16,64.1 16.5,64.6 18.5,64.6 20.505,66.605 21.3,66.605
  Top Layer w0.5: C31.2@22.9,56.5 22.9,57.9 21.3,59.5 C30.2@21.3,60.9 21.3,66.605 U4.4@22.718,66.605 22.723,66.6 23.6,66.6 24.1,66.1 R39.1@25,66.1 C32.2@26.6,66.1
  Top Layer w1: D16.1@9.369,63.6 9.369,60.731 11.55,58.55 L8.1@13.7,58.55 ; R37.2@14.6,63.55 13.7,62.65 L8.1@13.7,58.55 ; L8.1@15,58.55 L8.1@13.7,58.55
NetC32_1: C32.1 D9.2 D10.1 R36.2 R38.2 | length 19.9
  Top Layer w0.5: R36.2@26.65,62.9 26.65,64.45 C32.1@26.6,64.5 28,64.5 29.4,63.1 29.4,56.1 28.1,54.8 D9.2@27.9,54.8 27.9,53.35 D10.1@28.7,52.55
  Top Layer w0.8: R38.2@25.625,52.1 26.8,52.1 27.25,52.55 D10.1@28.7,52.55
NetC33_1: C33.1 L6.1 U5.2 | length 5.8
  Top Layer w0.5: C33.1@24.3,33.595 24.3,35.8 24.7,36.2 U5.2@25.412,36.2 25.462,36.25 26.85,36.25 27.15,36.55 L6.1@27.15,37
NetC33_2: C33.2 U5.6 | length 1.7
  Top Layer w0.4: U5.6@22.662,35.25 22.681,35.231 22.681,33.614 C33.2@22.7,33.595
NetC37_2: C37.2 L7.2 Q2.2 U4.8 | length 39.9
  Top Layer w0.5: v2(17.182,62.02) 17.182,62.613 U4.8@17.268,62.795
  Top Layer w1: v2(11.2,76.2) 14.7,76.2 Q2.2@15.1,75.8 Q2.2@13.1,75.8
  Bottom Layer w0.5: C37.2@8.5,72.6 8.5,70.701 v2(17.182,62.02)
  Bottom Layer w1: C37.2@8.5,72.6 10.06,72.6 11.2,73.74 v2(11.2,76.2) ; C37.2@8.6,72.7 8.6,79.598 9.852,80.85 L7.2@14.4,80.85
NetC38_1: C38.1 D12.1 L7.1 | length 11.4
  Top Layer w1: L7.1@14.35,83.4 L7.1@14.4,83.35 16.4,83.35 17.15,82.6 D12.1@19.3,82.6
  Bottom Layer w1: C38.1@8.3,83.4 14.35,83.4 L7.1@14.4,83.35
NetC39_1: C39.1 C40.1 D10.2 D11.1 D15.1 L8.2 R38.1 R41.1 R44.2 TP26.1
NetC49_1: C49.1 J9.105 R75.1 | length 9.9
  Top Layer w0.5: J9.105@85,23 85,17.3 85.5,16.8 C49.1@87.4,16.8 R75.1@89,16.8
NetC57_1: C57.1 Q3.2 Q4.3 | length 7.9
  Top Layer w0.5: C57.1@90.55,1.9 92.225,1.9 92.825,2.5 Q4.3@94.5,2.5 94.5,3.1 96.4,5 Q3.2@96.4,5.4
NetC60_2: C60.2 R87.1 | length 1.9
  Top Layer w1: R87.1@63.1,7.5 63.1,7.058 64.05,6.108 C60.2@64.05,6
NetC62_1: C62.1 Q6.1 R88.2 | length 3.2
  Top Layer w0.5: Q6.1@65.4,9.5 65.45,9.55 66.805,9.55 C62.1@66.905,9.65 R88.2@68.49,9.65
NetD1_1: D1.1 D3.1 K1.3 | length 31.9
  Top Layer w0.5: K1.3@48.42,46.78 51.535,43.665 63.646,43.665 66.041,41.27 68.83,41.27 69.5,40.6
  Top Layer w1: D1.1@40.4,46.3 47.94,46.3 K1.3@48.42,46.78
NetD1_2: D1.2 D2.1 | length 6.8
  Top Layer w0.5: D2.1@39.8,43.1 D2.1@40.407,43.1
  Top Layer w0.8: D1.2@36.4,46.3 38,46.3 38.3,46 38.3,43.475 38.675,43.1 D2.1@39.8,43.1
NetD3_2: D3.2 K1.4 Q1.3 TP9.1 | length 19.8
  Top Layer w1: K1.4@58.58,46.78 60.57,44.79 64.81,44.79 66.8,42.8 69.5,42.8 ; Q1.3@71.3,41.1 71.3,41.9 70.4,42.8 69.5,42.8 ; TP9.1@72.6,44.2 69.9,44.2 69.5,43.8 69.5,42.8
NetD11_2: D11.2 J8.1
NetD13_2: D13.2 R43.2 | length 2.2
  Top Layer w0.5: D13.2@32.1,39.8 R43.2@34.3,39.8
NetD14_2: D14.2 R45.1 | length 1.7
  Top Layer w0.5: D14.2@29.5,45.8 R45.1@31.25,45.8
NetD17_1: D17.1 R76.1 | length 1.9
  Top Layer w0.5: D17.1@73.3,14.95 74.85,14.95 R76.1@75.1,15.2
NetD18_1: D18.1 R77.1 | length 1.8
  Top Layer w0.5: R77.1@76.7,15.2 76.89,15.01 D18.1@78.4,15.01
NetJ9_54: J9.54 R55.1 | length 12.4
  Top Layer w0.25: J9.54@61,26.4 61,25.4 61.2,25.2 63.5,25.2 64,24.7 64,17.4 R55.1@64.6,16.8
NetJ9_56: J9.56 R57.1 | length 12.7
  Top Layer w0.25: J9.56@61.8,26.4 63.4,26.4 64.5,25.3 64.5,19.05 65.45,18.1 66,18.1 66.2,17.9 R57.1@66.2,16.8
NetJ9_57: J9.57 R63.1 | length 10.7
  Top Layer w0.5: J9.57@65.8,23 65.8,20.4 66.6,19.6 69.137,19.6 70.137,18.6 71,18.6 71.5,18.1 R63.1@71.5,16.7
NetJ9_62: J9.62 R65.1 | length 4.6
  Top Layer w0.5: J9.62@67.4,26.4 R65.1@67.4,31
NetJ9_99: J9.99 R70.2 | length 6.6
  Top Layer w0.5: R70.2@81.527,16.8 81.527,18.626 82.6,19.7 J9.99@82.6,23
NetJ9_101: J9.101 R73.2 | length 6.3
  Top Layer w0.5: R73.2@83.1,16.8 83.1,18.3 83.4,18.6 J9.101@83.4,23
NetJ10_6: J10.6 R54.2 | length 4.9
  Top Layer w1: J10.6@33.65,6.8 33.65,10.05 R54.2@34.8,11.2
NetJ10_8: J10.8 R52.2 | length 5.2
  Top Layer w1: J10.8@36.19,6.8 36.291,6.901 36.291,7.901 38.1,9.71 R52.2@38.1,11.2
NetJ10_10: J10.10 R51.2 | length 5.5
  Top Layer w1: J10.10@38.73,6.8 38.831,6.901 38.831,8.151 41.362,10.682 R51.2@41.362,11.2
NetJ10_12: J10.12 R50.2 | length 6.6
  Top Layer w1: J10.12@41.27,6.8 41.371,6.901 41.371,8.634 41.957,9.22 43.425,9.22 44.6,10.395 R50.2@44.6,11.2
NetJ10_14: J10.14 R49.2 | length 6.1
  Top Layer w1: J10.14@43.81,6.8 47.9,10.89 R49.2@47.9,11.2
NetJ10_16: J10.16 R48.2 | length 7.4
  Top Layer w1: J10.16@46.35,6.8 46.37,6.8 48.27,8.7 49.9,8.7 51.2,10 R48.2@51.2,11.2
NetJ11_2: J11.2 R74.2 | length 4.7
  Top Layer w1: J11.2@16.6,27 R74.2@21.3,27
NetJ11_4: J11.4 R71.2 | length 4.7
  Top Layer w0.95: J11.4@16.6,24.46 18.293,24.46 18.3,24.467 R71.2@21.3,24.467
NetJ11_6: J11.6 R69.2 | length 4.7
  Top Layer w0.95: J11.6@16.6,21.92 21.287,21.92 R69.2@21.3,21.933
